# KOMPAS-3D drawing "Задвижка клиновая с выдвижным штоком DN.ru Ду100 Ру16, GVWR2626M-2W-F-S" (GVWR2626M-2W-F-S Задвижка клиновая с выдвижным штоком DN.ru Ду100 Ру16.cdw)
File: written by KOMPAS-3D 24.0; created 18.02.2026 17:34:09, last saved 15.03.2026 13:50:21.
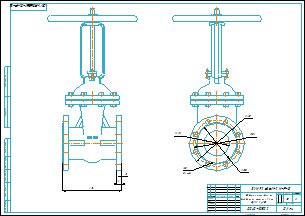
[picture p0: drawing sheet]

Document properties: Автор: R2D2; Форматы листов документа: A2; Полное имя файла: GVWR2626M-2W-F-S Задвижка клиновая с выдвижным штоком DN.ru Ду100 Ру16.m3d; Масса: 35; Наименование: Задвижка клиновая с выдвижным штоком DN.ru Ду100 Ру16; Количество листов документа: 1; Примечание: D040-10502

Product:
- Part/product: Задвижка клиновая с выдвижным штоком DN.ru Ду100 Ру16  | designation GVWR2626M-2W-F-S
    Масса: 35
    Раздел спецификации: Прочие изделия
    Примечание: D040-10502

Referenced files in E:\Работа\Зайцев\Для компаса\: чертеж DN.ru А3.cdt
Referenced files in E:\Работа\Зайцев\GVWR2626M-2W-F-S Задвижка клиновая с выдвижным штоком DN.ru Ду50-300 Ру16\DN100\: GVWR2626M-2W-F-S Задвижка клиновая с выдвижным штоком DN.ru Ду100 Ру16.m3d
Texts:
  чертеж DN.ru А3.cdt
  Задвижка клиновая с
  выдвижным штоком DN.ru
  Ду100 Ру16
  GVWR2626M-2W-F-S
  Задвижка клиновая с выдвижным штоком DN.ru Ду100 Ру16
  GVWR2626M-2W-F-S Задвижка клиновая с выдвижным штоком DN.ru Ду100 Ру16
Dimensions and other numbers on the sheet: 1:2; 0; 1; 2; 35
